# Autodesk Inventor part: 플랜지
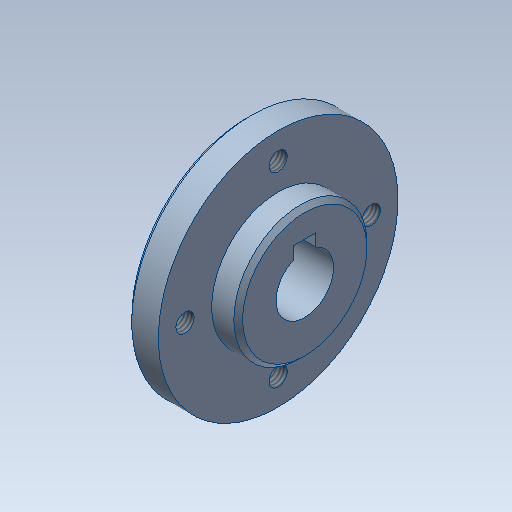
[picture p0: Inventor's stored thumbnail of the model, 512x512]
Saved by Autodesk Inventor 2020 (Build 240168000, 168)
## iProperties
Created: 2024-02
Part Number: 플랜지
Material: 강철, 탄소
Document SubType Name: Modeling
Designer: mdu-01
Density: 1 g/cm^3
Appearance: 기본값(1)
Author: mdu-01
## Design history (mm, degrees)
sketch "스케치1"
  geometry: L1 (0, 0)-(22, 0); L2 (0, -6.5)-(0, -11); L3 (0, -11)-(9, -11); L4 (9, -11)-(9, -26); L5 (10, -27)-(16, -27); L6 (16, -27)-(16, -15); L7 (16, -15)-(21, -15); L8 (22, -14)-(22, -6.5); L9 (22, -6.5)-(0, -6.5); L10 (21, -15)-(22, -14); L11 (9, -26)-(10, -27); L12 (0, 0)-(0, 8.8); L13 (0, 8.8)-(22, 8.8); L14 (22, 8.8)-(22, 0); 2 further points
  constraints: 28 end point, 6 parallel, 6 point on line, 4 perpendicular, 1 horizontal, 1 vertical
  dimensions: "d0" = 22 distance of L1.start L1.end; "d1" = 54 diameter of L5 L1; "d2" = 22 diameter of L3 L1; "d3" = 13 diameter of L9 L1; "d4" = 9 distance between parallel lines of L4 L2; "d5" = 6 distance between parallel lines of L8 L6; "d6" = 30 diameter of L7 L1; "d7" = 1 distance of L7.end point (22, -15); "d8" = 1 distance of L8.start point (22, -15) (= d7); "d9" = 1 distance of L4.end point (9, -27) (= d7); "d10" = 1 distance of L5.start point (9, -27) (= d9); "d11" = 15.3 distance between parallel lines of L13 L9
revolve "회전1" stored, may be unused: angle "d12" = 90 deg
extrude "돌출1" cut sketch "스케치1" stored distance "d13" = 5; taper "d14" = 0 deg
chamfer "모따기1" distance "d15" = 1; stored, may be unused: second distance "d16" = 2, angle "d17" = 45 deg
sketch "스케치2" dims "d18" = 42
  geometry: 3 further points
  constraints: 2 vertical alignment, 1 coincident, 2 other
hole "구멍1" sketch "스케치2" at (0, 21) diameter "d20" = 4.134; stored, may be unused: countersink angle "d24" = 90 deg, drill point angle "d26" = 118 deg; dims "d21" = 6, "d22" = 4, "d23" = 2, "d25" = 8
node "솔리드1"
pattern_circular "원형 패턴1" dims angle "d28" = 360 deg
